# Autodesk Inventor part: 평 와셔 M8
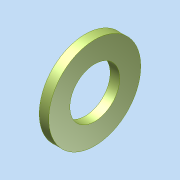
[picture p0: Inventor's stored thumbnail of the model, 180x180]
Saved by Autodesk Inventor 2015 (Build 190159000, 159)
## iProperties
Created: 2026-09
Part Number: 평 와셔 M8
Material: 일반
Document SubType Name: Modeling
Designer: SCD-A06
Density: 1 g/cm^3
Appearance: 기본값
Author: SCD-A06
Author: jhkim
Description: 평면 와셔
Creation Date: 2026-08-27
Sending System: Autodesk Inventor 2027
Preprocessor: ST-DEVELOPER v20.1
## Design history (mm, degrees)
node "평 와셔 M81"
body "Solid1"
node "기준1"
